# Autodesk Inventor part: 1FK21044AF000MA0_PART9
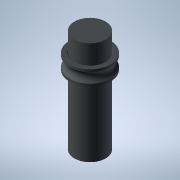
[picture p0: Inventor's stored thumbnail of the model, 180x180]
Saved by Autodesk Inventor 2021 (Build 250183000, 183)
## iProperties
Created: 2025-04
Part Number: 1FK21044AF000MA0_PART9
Material: Generic
Catalog Web Link: www.3dfindit.com
Description: -Servo synchronous motor
Document SubType Name: Modeling
Designer: psAdmin
Mass: 18.6788 g
Surface Area: 52.316 cm^2
Volume: 18.6788 cm^3
Density: 1 g/cm^3
Appearance: PSOLRGB-212-217-219
Category: PARTsolutions
Title: 1FK21044AF000MA0_PART9
Author: Cadenas PARTsolutions
Comments: Servo synchronous motor
Sending System: PARTsolutions
Preprocessor: ST-DEVELOPER v19.3
PSOL_IDENT_0: {$CADENAS_DATA/23d-libs/siemens_ag/_cat_/39/c4/1fk21044af000ma0.prj},213 {VTYP=3D},{NB=1FK21044AF000
PSOL_IDENT_1: MA0_PART9},{LINA=1FK21044AF000MA0_PART9},{NN=1FK21044AF000MA0_PART9},{NOPRJ=TRUE},{DATE=19.08.2025 1
PSOL_IDENT_2: 4:00:33},{GEOMDATE=30.07.2025 02:02:22},{VERSION=},{LINEID=10},{WBVAR=},{WBNUMERIC=}  {NB=1FK21044AF
PSOL_IDENT_3: 000MA0_PART9},{LINA=1FK21044AF000MA0_PART9},{KT=DUMMY},{PREVIEW=../../../_pool_/cb/72/p_d211_xx_0043
PSOL_IDENT_4: 4j.png},{DESCSHORT=SIMOTICS S-1FK2 HD, SINAMICS S210 3AC 400V-480V, 1.27 Nm, 3000 rpm},{DESCLONG=SIM
PSOL_IDENT_5: OTICS S-1FK2 HD servo motor M0=1.27 Nm; PN = 0.4 kW at nN=3000 rpm (380-480 V); PN = 0.2 kW at nN=15
PSOL_IDENT_6: 00 rpm (200-240 V); degree of protection IP64; cylindrical shaft D19x40mm; absolute encoder 22-bit +
PSOL_IDENT_7: 12-bit multiturn (encoder AM22DQC); with OCC interface; plug size M17, rotatable; SIMOTICS S-1FK2 s
PSOL_IDENT_8: ervomotorfor a wide range of uses in industrial environments. SIMOTICS S‑1FK2 servomotors are compac
PSOL_IDENT_9: t synchronous motors with a high dynamic performance that set themselves apart as a result of their
PSOL_IDENT_10: high power density, degree of protection and overload capability. The motors are available in two va
PSOL_IDENT_11: riants: as High Dynamic variant (highest dynamic performance as a result of the low intrinsic moment
PSOL_IDENT_12: of inertia for applications demanding a high dynamic performance with low moved masses) - and as Co
PSOL_IDENT_13: mpact variant (precise and stable closed-loop control for medium up to large moved masses as a resul
PSOL_IDENT_14: t of a medium intrinsic moment of inertia). SIMOTICSS‑1FK2 servomotors fully exploit their strengths
PSOL_IDENT_15: in a system with the SINAMICSS210 frequency converter and simple connection using the one cable con
PSOL_IDENT_16: nection (OCC). Advantages include the short control and positioning times, fast and precise correcti
PSOL_IDENT_17: on of disturbing quantities as well as stable control with a high dynamic performance. The servo mot
PSOL_IDENT_18: ors can be configured to address a wide range of requirements. For example with and without holding
PSOL_IDENT_19: brake, IP64 or IP65 degree of protection, singleturn or multiturn absolute encoders - to name just a
PSOL_IDENT_20: few. Further, the servomotors are available in different shaft heights extending from 20 to 100. A
PSOL_IDENT_21: shaft sealing ring is available to achieve an IP65 degree of protection and for subsequent mounting
PSOL_IDENT_22: at the motor or as spare part. SIMOTICS - the optimum motor for each and every motion control applic
PSOL_IDENT_23: ation.},{INTNO=804766906428},{SUPPLIERALTNO=1FK2104-4AF00-0MA0},{MANUID=1FK21044AF000MA0},{MANUNAME=
PSOL_IDENT_24: Siemens},{MANUTYPEDESC=Synchronous motor 1FK2-HD 1.27 NM},{AAU732=SIMOTICS},{AAO057=S-1FK2},{AAU734=
PSOL_IDENT_25: SIMOTICS S-1FK2 HD servo motor M0=1.27 Nm; PN = 0.4 kW at nN=3000 rpm (380-480 V); PN = 0.2 kW at nN=
PSOL_IDENT_26: 1500 rpm (200-240 V); degree of protection IP64; cylindrical shaft D19x40mm; absolute encoder 22-bit
PSOL_IDENT_27: + 12-bit multiturn (encoder AM22DQC); with OCC interface; plug size M17, rotatable;},{AAW338=Synchr
PSOL_IDENT_28: onous motor 1FK2-HD 1.27 NM},{AAO742=SIMOTICS},{AAO663=4042948693322},{NOCUPEROU=1},{PRICEQUANTITY=1
PSOL_IDENT_29: },{QUANTITYMIN=1},{QUANTITYINT=1},{CTN=85015100},{COO=DE},{AAO676=1FK2104-4AF00-0MA0},{AAO677=Siemen
PSOL_IDENT_30: s AG},{ORDERUNIT=C62},{CONTENTUNIT=C62}
NB: 1FK21044AF000MA0_PART9
NT: Servo synchronous motor
NBSYN: $MANUID._PART9
LINA: 1FK21044AF000MA0_PART9
CATALOG: SIEMENS
PREVIEW: ../../../_pool_/cb/72/p_d211_xx_00434j.png
DESCSHORT: SIMOTICS S-1FK2 HD, SINAMICS S210 3AC 400V-480V, 1.27 Nm, 3000 rpm
DESCLONG: SIMOTICS S-1FK2 HD servo motor M0=1.27 Nm; PN = 0.4 kW at nN=3000 rpm (380-480 V); PN = 0.2 kW at nN=1500 rpm (200-240 V); degree of protection IP64; cylindrica
INTNO: 804766906428
SUPPLIERALTNO: 1FK2104-4AF00-0MA0
MANUID: 1FK21044AF000MA0
MANUNAME: Siemens
MANUTYPEDESC: Synchronous motor 1FK2-HD 1.27 NM
AAU732: SIMOTICS
AAO057: S-1FK2
AAU734: SIMOTICS S-1FK2 HD servo motor M0=1.27 Nm; PN = 0.4 kW at nN=3000 rpm (380-480 V); PN = 0.2 kW at nN=1500 rpm (200-240 V); degree of protection IP64; cylindrica
AAW338: Synchronous motor 1FK2-HD 1.27 NM
AAO742: SIMOTICS
AAO663: 4042948693322.0
NOCUPEROU: 1
PRICEQUANTITY: 1
QUANTITYMIN: 1
QUANTITYINT: 1
CTN: 85015100
COO: DE
ARTICLENO: 1FK21044AF000MA0_PART9
BOMINFO: 1FK21044AF000MA0_PART9
CREATOR: CADENAS GmbH
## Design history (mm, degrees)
feature "2025_04_17_15_01_28_0038"
body "Solid1"
